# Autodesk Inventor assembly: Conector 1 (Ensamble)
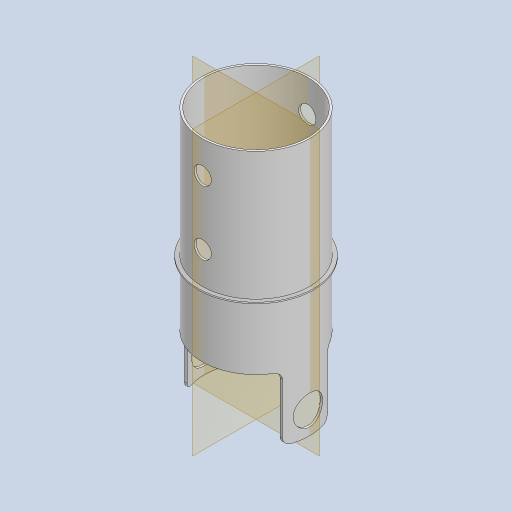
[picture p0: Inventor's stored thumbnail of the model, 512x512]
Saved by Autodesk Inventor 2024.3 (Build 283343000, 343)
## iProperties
Created: 2025-10
Part Number: Conector 1 (Ensamble)
Document SubType Name: Assembly
Designer: Asus
Author: Asus
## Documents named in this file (4)
- D:\2025\Anclajes Guadua\Conector a Guadua (Ensamble).iam
- D:\2025\Anclajes Guadua\Tuberia Interior.ipt
- D:\2025\Anclajes Guadua\Disco Soporte.ipt
- D:\2025\Anclajes Guadua\Tuberia Conector 1.ipt
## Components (3 placed, 3 different names)
1. Tuberia Interior:1 — Nivelación:1, Nivelación:2, Coincidencia:1, Coincidencia:2, Coincidencia:4, Coincidencia:6
2. Disco Soporte:1 — Coincidencia:2, Nivelación:3, Coincidencia:3, Coincidencia:4, Coincidencia:5
3. Tuberia Conector 1:1 — Coincidencia:5, Coincidencia:6, Nivelación:4
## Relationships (10: Mate 6, Flush 4)
- Nivelación:1 [Flush]: Tuberia Interior:1
- Nivelación:2 [Flush]: Tuberia Interior:1
- Coincidencia:1 [Mate]: Tuberia Interior:1
- Coincidencia:2 [Mate]: Tuberia Interior:1 ↔ Disco Soporte:1
- Nivelación:3 [Flush]: Disco Soporte:1
- Coincidencia:3 [Mate]: Disco Soporte:1
- Coincidencia:4 [Mate]: Tuberia Interior:1 ↔ Disco Soporte:1
- Coincidencia:5 [Mate]: Disco Soporte:1 ↔ Tuberia Conector 1:1
- Coincidencia:6 [Mate]: Tuberia Interior:1 ↔ Tuberia Conector 1:1
- Nivelación:4 [Flush]: Tuberia Conector 1:1
